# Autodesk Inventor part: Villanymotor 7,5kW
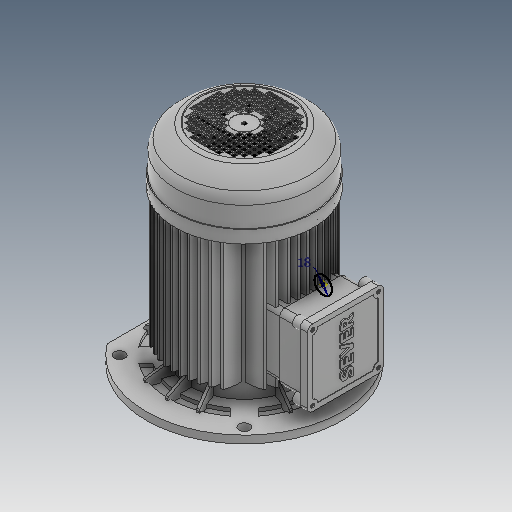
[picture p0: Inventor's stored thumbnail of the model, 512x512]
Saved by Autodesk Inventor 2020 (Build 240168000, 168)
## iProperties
Created: 2015-05
Part Number: Villanymotor 7,5kW
Material: Hliník 6061
Document SubType Name: Modeling
Designer: doma
Density: 2.7 g/cm^3
Appearance: Hladká – středně šedá
Mass: 6175.77 g
Surface Area: 4254.78 cm^2
Volume: 2287.32 cm^3
Sending System: SolidWorks 2013
Last Author: h
Last Saved: 2015-12-01
Author: doma
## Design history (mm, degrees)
feature "Boss-Extrude9[1]" [Revolve]
feature "Boss-Extrude9[2]" [Revolve]
feature "Boss-Extrude9[3]" [Revolve]
feature "Boss-Extrude9[4]" [Revolve]
feature "Boss-Extrude13" [Revolve]
feature "Boss-Extrude14" [Revolve]
feature "Revolve3"
feature "Boss-Extrude15" [Revolve]
feature "CirPattern11[1]" [Revolve]
feature "CirPattern11[2]" [Revolve]
feature "CirPattern11[3]" [Revolve]
feature "CirPattern11[4]" [Revolve]
feature "CirPattern11[5]" [Revolve]
feature "CirPattern11[6]" [Revolve]
feature "CirPattern11[7]" [Revolve]
feature "CirPattern11[8]" [Revolve]
feature "CirPattern11[9]" [Revolve]
feature "CirPattern11[10]" [Revolve]
feature "CirPattern11[11]" [Revolve]
feature "CirPattern11[12]" [Revolve]
feature "CirPattern11[13]" [Revolve]
feature "CirPattern11[14]" [Revolve]
node "Upravit přímo2"
sketch "Náčrt2"
  geometry: C1 r 4.839 at (-62.271, 62.271) reference; C2 r 4.839 at (62.271, 62.271) reference; C3 r 4.839 at (62.271, -62.271) reference; C4 r 4.839 at (-62.271, -62.271) reference; 5 further points
  constraints: 4 coincident
hole "Díra1" sketch "Náčrt2" at (-62.271, 62.271), (62.271, 62.271), (62.271, -62.271), (-62.271, -62.271) diameter "d6" = 10; stored, may be unused: countersink angle "d10" = 90 deg, drill point angle "d12" = 118 deg; dims "d7" = 6, "d8" = 4, "d9" = 2, "d11" = 10
node "Upravit přímo3"
node "Upravit přímo4"
sketch "Náčrt3"
  geometry: C1 r 7.226 at (0, 0) reference; C2 r 100 at (0, 0); C3 r 80 at (0, 0) reference; 1 further point
  constraints: 1 centre point, 1 coincident
  dimensions: "d19" = 200 diameter of C2
extrude "Vysunutí1" join sketch "Náčrt3" stored distance "d20" = 10; taper "d21" = 0 deg
sketch "Náčrt4" dims "d22" = 180
  geometry: L1 (63.64, 63.64)-(0, 0); L2 (95.484, 38.71)-(103.226, 38.71) reference; C1 r 15.484 at (0, 0) reference; C2 r 7.742 at (0, 0) reference; C3 r 2.065 at (0, 0) reference; 5 further points
  constraints: 2 end point, 1 coincident, 8 other
  dimensions: "d23" = 45 deg angle of L2 L1; "d26" = 360 deg dimension on point (0, 0) L1.start (derived)
hole "Díra2" sketch "Náčrt4" at (63.64, 63.64), (-63.64, 63.64), (-63.64, -63.64), (63.64, -63.64) diameter "d28" = 11; stored, may be unused: countersink angle "d32" = 90 deg, drill point angle "d34" = 118 deg; dims "d29" = 6, "d30" = 4, "d31" = 2, "d33" = 10
node "Upravit přímo5"
sketch "Náčrt5"
  geometry: L1 (-145.463, -85.338)-(-145.463, 109.388); L2 (-145.463, 109.388)-(-80, 109.388); L3 (-80, 109.388)-(-80, -85.338); L4 (-80, -85.338)-(-145.463, -85.338); C1 r 100 at (0, 0) reference; 1 further point
  constraints: 8 end point, 2 parallel, 1 perpendicular
  dimensions: "d35" = 80 distance from line of C1.centre L3
extrude "Vysunutí2" cut sketch "Náčrt5" distance "d36" = 10; taper "d37" = 0 deg
sketch "Náčrt6"
  geometry: C1 r 9 at (80.01, -39.044); 1 further point
  constraints: 1 centre point
  dimensions: "d38" = 18 diameter of C1
node "Pracovní bod1"
sketch "Náčrt7"
  geometry: L1 (0, 0)-(25.806, 0) reference; L2 (0, 61.935)-(25.806, 61.935) reference; L3 (14.993, 0)-(14.993, 56.774); L4 (25.806, 56.774)-(0, 56.774) reference; C1 r 5 at (14.993, 28.387); 1 further point
  constraints: 2 end point, 2 point on line, 1 centre point, 1 midpoint, 1 vertical
  dimensions: "d39" = 10 diameter of C1
extrude "Vysunutí3" join sketch "Náčrt7" distance "d40" = 8; taper "d41" = 0 deg
node "Těleso1"
node "Těleso2"
node "Těleso3"
node "Těleso4"
node "Těleso5"
node "Těleso6"
node "Těleso7"
node "Těleso8"
node "Těleso9"
node "Těleso10"
node "Těleso11"
node "Těleso12"
node "Těleso13"
node "Těleso14"
node "Těleso15"
node "Těleso16"
node "Těleso17"
node "Těleso18"
node "Těleso19"
node "Těleso20"
node "Těleso21"
node "Těleso22"
feature "Měřítko2"
feature "Měřítko3"
feature "Měřítko4"
feature "Odstranit1"
other parameters: "d3" = 6.45161, "d13" = 9, "d16" = 8.88889
